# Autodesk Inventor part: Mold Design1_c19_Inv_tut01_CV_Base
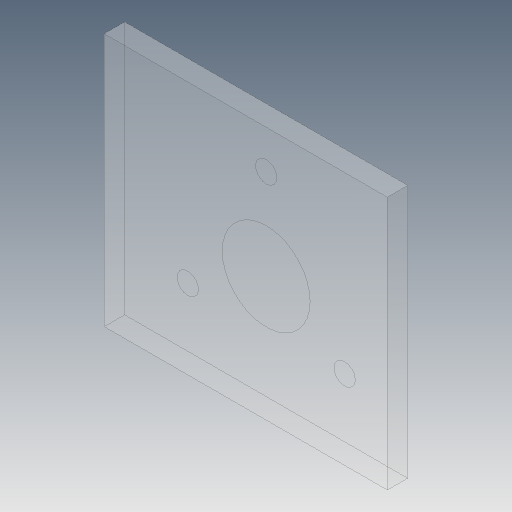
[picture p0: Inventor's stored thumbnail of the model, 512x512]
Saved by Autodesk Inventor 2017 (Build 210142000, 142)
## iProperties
Created: 2016-07
Part Number: Mold Design1_c19_Inv_tut01_CV_Base
Material: Generic
Document SubType Name: Modeling
Designer: Sandeep
Density: 1 g/cm^3
Appearance: Default
Author: Sandeep
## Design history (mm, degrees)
node "Mold Design1_c19_Inv_tut01_MP"
feature "Solid4::Mold Design1_c19_Inv_tut01_MP"
tag "TaggingFeature1"
body "Solid1"
feature "Mold Design1_c19_Inv_tut01_MP_Bodies"
